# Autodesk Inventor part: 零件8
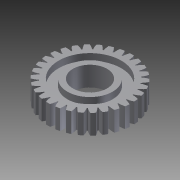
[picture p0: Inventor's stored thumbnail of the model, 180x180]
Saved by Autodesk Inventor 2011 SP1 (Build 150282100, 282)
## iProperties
Created: 2014-02
Part Number: 零件8
Document SubType Name: Modeling
Designer: yn
Density: 1 g/cm^3
Author: yn
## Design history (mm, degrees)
sketch "草图1"
  geometry: C1 r 32 at (0, 0); C2 r 12.981 at (0, 0); C3 r 32 at (0, 0); C4 r 32 at (0, 0); C5 r 32 at (0, 0); C6 r 32 at (0, 0); C7 r 32 at (0, 0); C8 r 32 at (0, 0); C9 r 32 at (0, 0); C10 r 32 at (0, 0); C11 r 32 at (0, 0); C12 r 32 at (0, 0); C13 r 32 at (0, 0); C14 r 32 at (0, 0); C15 r 32 at (0, 0); C16 r 32 at (0, 0); C17 r 32 at (0, 0); C18 r 32 at (0, 0); C19 r 32 at (0, 0); C20 r 32 at (0, 0); C21 r 32 at (0, 0); C22 r 32 at (0, 0); C23 r 32 at (0, 0); C24 r 32 at (0, 0); C25 r 32 at (0, 0); C26 r 32 at (0, 0); C27 r 32 at (0, 0); C28 r 32 at (0, 0); C29 r 32 at (0, 0); C30 r 32 at (0, 0); C31 r 32 at (0, 0); A1 r 27.5 centre (0, 0) between (2.568, 27.38) and (-2.568, 27.38); A2 r 32 centre (0, 0) between (-31.629, 4.856) and (-30.87, 8.428); A3 r 16.434 centre (13.812, 26.057) between (-1.524, 31.964) and (-2.568, 27.38); A4 r 16.434 centre (-13.812, 26.057) between (2.568, 27.38) and (1.524, 31.964); A5 r 16.434 centre (8.093, 28.36) between (-8.136, 30.948) and (-8.205, 26.248); A6 r 16.434 centre (-18.928, 22.616) between (-3.18, 27.315) and (-5.155, 31.582); A7 r 16.434 centre (2.02, 29.423) between (-14.393, 28.581) and (-13.483, 23.968); A8 r 16.434 centre (-23.217, 18.187) between (-8.79, 26.057) and (-11.609, 29.82); A9 r 16.434 centre (-4.142, 29.2) between (-20.02, 24.964) and (-18.171, 20.641); A10 r 16.434 centre (-26.49, 12.962) between (-14.016, 23.66) and (-17.555, 26.755); A11 r 16.434 centre (-10.122, 27.7) between (-24.773, 20.256) and (-22.066, 16.412); A12 r 16.434 centre (-28.607, 7.171) between (-18.629, 20.229) and (-22.734, 22.52); A13 r 16.434 centre (-15.66, 24.99) between (-28.443, 14.662) and (-24.996, 11.466); A14 r 16.434 centre (-29.472, 1.067) between (-22.427, 15.914) and (-26.92, 17.301); A15 r 16.434 centre (-20.514, 21.188) between (-30.87, 8.428) and (-26.833, 6.018); A16 r 16.434 centre (-29.05, -5.084) between (-25.246, 10.903) and (-29.928, 11.326); A17 r 16.434 centre (-24.471, 16.46) between (-31.948, 1.826) and (-27.498, 0.308); A18 r 16.434 centre (-27.358, -11.013) between (-26.961, 5.416) and (-31.629, 4.856); A19 r 16.434 centre (-27.358, 11.013) between (-31.629, -4.856) and (-26.961, -5.416); A20 r 16.434 centre (-24.471, -16.46) between (-27.498, -0.308) and (-31.948, -1.826); A21 r 16.434 centre (-29.05, 5.084) between (-29.928, -11.326) and (-25.246, -10.903); A22 r 16.434 centre (-20.514, -21.188) between (-26.833, -6.018) and (-30.87, -8.428); A23 r 16.434 centre (-29.472, -1.067) between (-26.92, -17.301) and (-22.427, -15.914); A24 r 16.434 centre (-15.66, -24.99) between (-24.996, -11.466) and (-28.443, -14.662); A25 r 16.434 centre (-28.607, -7.171) between (-22.734, -22.52) and (-18.629, -20.229); A26 r 16.434 centre (-10.122, -27.7) between (-22.066, -16.412) and (-24.773, -20.256); A27 r 16.434 centre (-26.49, -12.962) between (-17.555, -26.755) and (-14.016, -23.66); A28 r 16.434 centre (-4.142, -29.2) between (-18.171, -20.641) and (-20.02, -24.964); A29 r 16.434 centre (-23.217, -18.187) between (-11.609, -29.82) and (-8.79, -26.057); A30 r 16.434 centre (2.02, -29.423) between (-13.483, -23.968) and (-14.393, -28.581); A31 r 16.434 centre (-18.928, -22.616) between (-5.155, -31.582) and (-3.18, -27.315); A32 r 16.434 centre (8.093, -28.36) between (-8.205, -26.248) and (-8.136, -30.948); A33 r 16.434 centre (-13.812, -26.057) between (1.524, -31.964) and (2.568, -27.38); A34 r 16.434 centre (13.812, -26.057) between (-2.568, -27.38) and (-1.524, -31.964); A35 r 16.434 centre (-8.093, -28.36) between (8.136, -30.948) and (8.205, -26.248); A36 r 16.434 centre (18.928, -22.616) between (3.18, -27.315) and (5.155, -31.582); A37 r 16.434 centre (-2.02, -29.423) between (14.393, -28.581) and (13.483, -23.968); A38 r 16.434 centre (23.217, -18.187) between (8.79, -26.057) and (11.609, -29.82); A39 r 16.434 centre (4.142, -29.2) between (20.02, -24.964) and (18.171, -20.641); A40 r 16.434 centre (26.49, -12.962) between (14.016, -23.66) and (17.555, -26.755); A41 r 16.434 centre (10.122, -27.7) between (24.773, -20.256) and (22.066, -16.412); A42 r 16.434 centre (28.607, -7.171) between (18.629, -20.229) and (22.734, -22.52); A43 r 16.434 centre (15.66, -24.99) between (28.443, -14.662) and (24.996, -11.466); A44 r 16.434 centre (29.472, -1.067) between (22.427, -15.914) and (26.92, -17.301); A45 r 16.434 centre (20.514, -21.188) between (30.87, -8.428) and (26.833, -6.018); A46 r 16.434 centre (29.05, 5.084) between (25.246, -10.903) and (29.928, -11.326); A47 r 16.434 centre (24.471, -16.46) between (31.948, -1.826) and (27.498, -0.308); A48 r 16.434 centre (27.358, 11.013) between (26.961, -5.416) and (31.629, -4.856); A49 r 16.434 centre (27.358, -11.013) between (31.629, 4.856) and (26.961, 5.416); A50 r 16.434 centre (24.471, 16.46) between (27.498, 0.308) and (31.948, 1.826); A51 r 16.434 centre (29.05, -5.084) between (29.928, 11.326) and (25.246, 10.903); A52 r 16.434 centre (20.514, 21.188) between (26.833, 6.018) and (30.87, 8.428); A53 r 16.434 centre (29.472, 1.067) between (26.92, 17.301) and (22.427, 15.914); A54 r 16.434 centre (15.66, 24.99) between (24.996, 11.466) and (28.443, 14.662); A55 r 16.434 centre (28.607, 7.171) between (22.734, 22.52) and (18.629, 20.229); A56 r 16.434 centre (10.122, 27.7) between (22.066, 16.412) and (24.773, 20.256); A57 r 16.434 centre (26.49, 12.962) between (17.555, 26.755) and (14.016, 23.66); A58 r 16.434 centre (4.142, 29.2) between (18.171, 20.641) and (20.02, 24.964); A59 r 16.434 centre (23.217, 18.187) between (11.609, 29.82) and (8.79, 26.057); A60 r 16.434 centre (-2.02, 29.423) between (13.483, 23.968) and (14.393, 28.581); A61 r 16.434 centre (18.928, 22.616) between (5.155, 31.582) and (3.18, 27.315); A62 r 16.434 centre (-8.093, 28.36) between (8.205, 26.248) and (8.136, 30.948); 1 further point
  constraints: 126 point on circle, 93 centre point, 4 coincident, 1 concentric, 301 other
  dimensions: "d0" = 55 diameter of A1; "d1" = 64 diameter of C1; "d6" = 360 deg dimension on A1.centre A3.centre (derived)
extrude "拉伸1" new body sketch "草图1" distance "d8" = 15; taper "d9" = 0 deg
sketch "草图2"
  geometry: C1 r 17.237 at (0, 0); C2 r 23.811 at (0, 0); A1 r 27.5 centre (0, 0) between (3.18, 27.315) and (2.568, 27.38) reference
  constraints: 2 centre point, 2 coincident
extrude "拉伸2" cut sketch "草图2" distance "d13" = 5; taper "d14" = 0 deg
node "工作平面1"
mirror "镜像1"
node "实体1"
pattern_circular "环形阵列1" dims angle "d11" = 360 deg
other parameters: "d15" = 7.5
